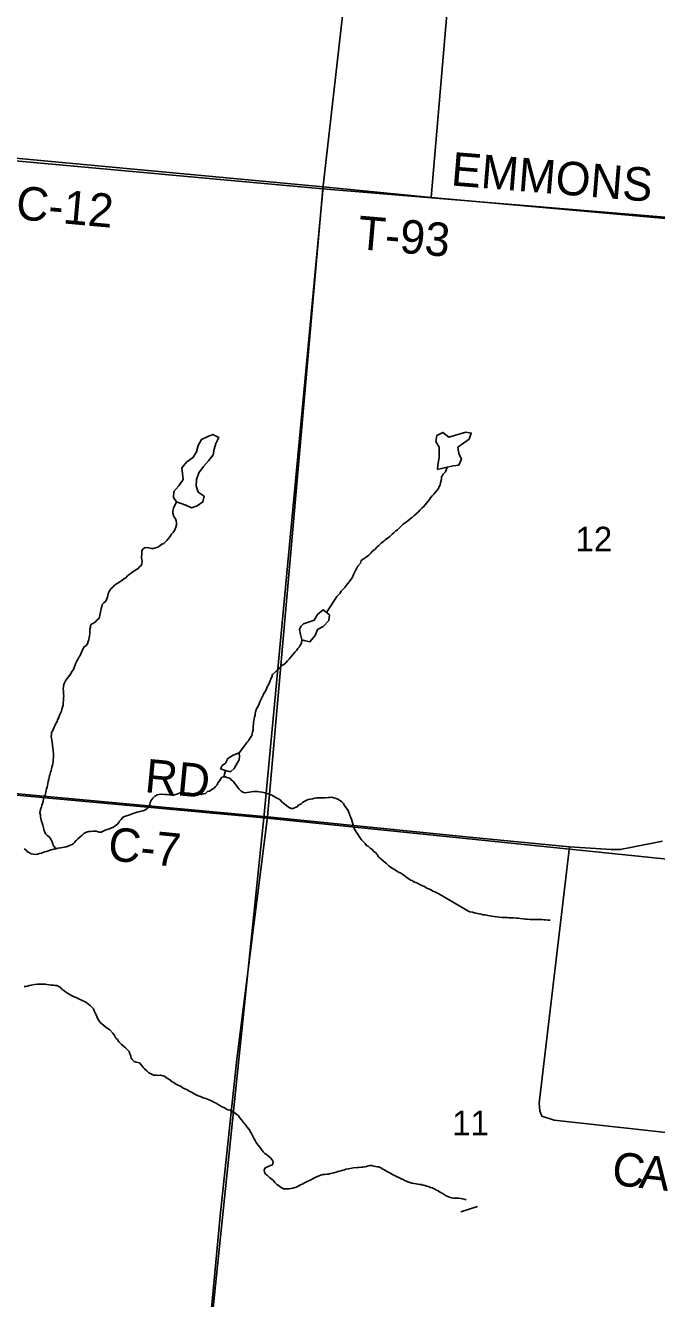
# Model space of a CAD drawing. Extents: x 1310247 to 1664935, y 284496 to 704931.
# Drawn here: x 1505542 to 1511194, y 520097 to 531499 of the extents above; entities that cross this region are included whole.
import ezdxf

# ---------------------------------------------------------------- set-up
doc = ezdxf.new("R2010")
doc.units = 0
for name, color, linetype in [('GM_X_County', 7, 'Continuous'), ('GM_X_County_Road_Text', 7, 'Continuous'), ('GM_X_County_Subdivision_Text', 7, 'Continuous'), ('GM_X_Minor_River', 7, 'Continuous'), ('GM_X_Minor_River_Text', 7, 'Continuous'), ('GM_X_Township_Road', 7, 'Continuous'), ('GM_X_Township_Subdivision', 7, 'Continuous'), ('GM_X_US_Location', 7, 'Continuous')]:
    doc.layers.add(name, color=color, linetype=linetype)

msp = doc.modelspace()

# ---------------------------------------------------------------- linework, layer by layer
at = {"layer": 'GM_X_County'}
for points in [[(1504265, 537212), (1509753, 536749), (1509752, 536706), (1509176, 529957), (1508208, 530054), (1503657, 530479)], [(1509752, 536706), (1515094, 536260), (1514552, 529479), (1513608, 529562), (1509176, 529957)], [(1503657, 530479), (1508208, 530054), (1507676, 524403), (1502528, 524873), (1503168, 530512)], [(1509176, 529957), (1513608, 529562), (1513069, 523850), (1507676, 524403), (1508208, 530054)], [(1502528, 524873), (1507676, 524403), (1507181, 519609), (1502005, 520104)], [(1513069, 523850), (1512615, 519096), (1507181, 519609), (1507676, 524403)]]:
    msp.add_lwpolyline(points, close=True, dxfattribs=at)
at = {"layer": 'GM_X_County_Road_Text'}
for points in [[(1505281, 530301), (1508204, 530036), (1508392, 531691)], [(1503046, 524841), (1507709, 524410), (1509518, 524229), (1510413, 524142), (1510508, 524135), (1510790, 524118), (1510869, 524118), (1510962, 524135), (1511247, 524193)]]:
    msp.add_lwpolyline(points, dxfattribs=at)
at = {"layer": 'GM_X_County_Subdivision_Text'}
for points in [[(1507709, 524410), (1508204, 530036)], [(1508204, 530036), (1513575, 529592)], [(1506888, 516735), (1507135, 519241), (1507286, 520838), (1507435, 522240), (1507709, 524410)], [(1512734, 520652), (1512746, 520753), (1512811, 521339), (1512781, 521407), (1512752, 521424), (1512685, 521430), (1510276, 521694), (1510168, 521730), (1510149, 521778), (1510143, 521846), (1510413, 524142)]]:
    msp.add_lwpolyline(points, dxfattribs=at)
at = {"layer": 'GM_X_Minor_River'}
for points in [[(1506894, 527231), (1506978, 527203), (1507029, 527178), (1507080, 527197), (1507131, 527231), (1507142, 527283), (1507089, 527319), (1507072, 527375), (1507075, 527432), (1507095, 527491), (1507137, 527549), (1507182, 527600), (1507224, 527653), (1507231, 527703), (1507246, 527755), (1507275, 527808), (1507220, 527836), (1507169, 527815), (1507118, 527792), (1507089, 527737), (1507075, 527679), (1507040, 527627), (1507038, 527625)], [(1509318, 527542), (1509373, 527555), (1509423, 527560), (1509447, 527613), (1509424, 527664), (1509413, 527721), (1509464, 527757), (1509515, 527794), (1509535, 527848), (1509485, 527855), (1509434, 527840), (1509384, 527826), (1509333, 527813), (1509280, 527854), (1509227, 527827), (1509218, 527773), (1509248, 527722), (1509247, 527674)], [(1507038, 527625), (1506987, 527590), (1506941, 527537), (1506948, 527487), (1506955, 527433), (1506915, 527377), (1506872, 527324), (1506869, 527272), (1506894, 527231)], [(1509247, 527674), (1509248, 527630), (1509235, 527562), (1509236, 527562)], [(1509236, 527562), (1509233, 527522), (1509318, 527542)], [(1508237, 526242), (1508209, 526266), (1508157, 526223), (1508128, 526171), (1508077, 526156), (1508033, 526139)], [(1508037, 525989), (1508089, 525979), (1508137, 526034), (1508158, 526088), (1508209, 526115), (1508258, 526170), (1508264, 526220), (1508237, 526242)], [(1508033, 526139), (1508012, 526120), (1507997, 526092), (1508004, 526044), (1508017, 525997), (1508037, 525989)], [(1507334, 524825), (1507364, 524818), (1507380, 524818), (1507412, 524843), (1507440, 524897), (1507455, 524921), (1507459, 524951), (1507456, 524983), (1507401, 524962), (1507354, 524933), (1507333, 524893), (1507305, 524872)], [(1507305, 524872), (1507290, 524842), (1507334, 524825)]]:
    msp.add_lwpolyline(points, dxfattribs=at)
at = {"layer": 'GM_X_Minor_River_Text'}
for points in [[(1508237, 526242), (1508311, 526353), (1508321, 526369), (1508330, 526385), (1508344, 526398), (1508357, 526412), (1508370, 526432), (1508380, 526445), (1508401, 526465), (1508415, 526484), (1508430, 526500), (1508445, 526519), (1508459, 526539), (1508470, 526557), (1508481, 526582), (1508492, 526604), (1508502, 526624), (1508511, 526638), (1508520, 526657), (1508543, 526683), (1508549, 526707), (1508593, 526737), (1508617, 526755), (1508634, 526774), (1508651, 526790), (1508673, 526809), (1508690, 526825), (1508706, 526842), (1508729, 526863), (1508750, 526879), (1508764, 526892), (1508785, 526908), (1508804, 526923), (1508826, 526943), (1508841, 526954), (1508859, 526972), (1508874, 526983), (1508895, 527003), (1508909, 527018), (1508926, 527032), (1508946, 527047), (1508963, 527059), (1508986, 527080), (1509004, 527092), (1509023, 527109), (1509041, 527124), (1509062, 527144), (1509074, 527157), (1509093, 527175), (1509106, 527189), (1509118, 527202), (1509137, 527222), (1509149, 527237), (1509160, 527253), (1509170, 527267), (1509185, 527286), (1509200, 527302), (1509216, 527321), (1509227, 527335), (1509240, 527353), (1509248, 527369), (1509255, 527382), (1509259, 527402), (1509264, 527422), (1509267, 527438), (1509269, 527456), (1509278, 527469), (1509282, 527481), (1509303, 527502), (1509318, 527542)], [(1506006, 525813), (1506015, 525827), (1506023, 525843), (1506032, 525856), (1506038, 525872), (1506045, 525886), (1506051, 525902), (1506058, 525916), (1506065, 525932), (1506087, 525947), (1506096, 525961), (1506104, 525980), (1506109, 525996), (1506111, 526014), (1506114, 526034), (1506117, 526048), (1506117, 526062), (1506117, 526076), (1506118, 526092), (1506123, 526110), (1506125, 526124), (1506134, 526138), (1506150, 526147), (1506170, 526157), (1506181, 526172), (1506199, 526186), (1506204, 526200), (1506209, 526218), (1506213, 526244), (1506216, 526260), (1506219, 526278), (1506225, 526295), (1506230, 526313), (1506244, 526327), (1506263, 526344), (1506269, 526358), (1506276, 526378), (1506279, 526394), (1506283, 526410), (1506288, 526424), (1506298, 526439), (1506307, 526453), (1506323, 526469), (1506340, 526486), (1506387, 526517), (1506406, 526528), (1506424, 526544), (1506441, 526553), (1506457, 526569), (1506472, 526582), (1506490, 526594), (1506507, 526607), (1506521, 526617), (1506535, 526625), (1506550, 526636), (1506562, 526650), (1506579, 526663), (1506583, 526677), (1506586, 526701), (1506585, 526715), (1506581, 526731), (1506581, 526745), (1506584, 526761), (1506583, 526777), (1506585, 526793), (1506594, 526807), (1506608, 526819), (1506626, 526822), (1506644, 526820), (1506658, 526817), (1506672, 526815), (1506686, 526814), (1506706, 526820), (1506727, 526827), (1506745, 526837), (1506762, 526852), (1506780, 526860), (1506795, 526873), (1506809, 526887), (1506820, 526900), (1506834, 526918), (1506851, 526942), (1506866, 526959), (1506876, 526977), (1506883, 526991), (1506889, 527006), (1506894, 527026), (1506895, 527044), (1506891, 527063), (1506886, 527079), (1506878, 527093), (1506869, 527111), (1506863, 527130), (1506862, 527148), (1506864, 527162), (1506869, 527179), (1506878, 527195), (1506894, 527231)], [(1507456, 524983), (1507513, 525059), (1507525, 525077), (1507536, 525090), (1507544, 525104), (1507557, 525122), (1507568, 525140), (1507572, 525155), (1507575, 525169), (1507581, 525189), (1507582, 525207), (1507582, 525223), (1507583, 525239), (1507584, 525257), (1507586, 525273), (1507589, 525291), (1507593, 525305), (1507598, 525323), (1507598, 525337), (1507601, 525351), (1507607, 525369), (1507614, 525383), (1507626, 525402), (1507635, 525422), (1507642, 525440), (1507650, 525460), (1507659, 525477), (1507670, 525501), (1507678, 525517), (1507689, 525535), (1507698, 525548), (1507704, 525566), (1507711, 525580), (1507719, 525594), (1507726, 525614), (1507734, 525631), (1507739, 525645), (1507748, 525665), (1507754, 525685), (1507785, 525712), (1507806, 525733), (1507825, 525751), (1507835, 525765), (1507856, 525776), (1507874, 525791), (1507889, 525809), (1507903, 525823), (1507912, 525836), (1507927, 525852), (1507937, 525866), (1507958, 525889), (1507972, 525905), (1507981, 525918), (1507993, 525932), (1508002, 525950), (1508013, 525964), (1508017, 525997)], [(1505814, 524123), (1505789, 524156), (1505788, 524170), (1505782, 524187), (1505773, 524205), (1505763, 524219), (1505750, 524234), (1505736, 524244), (1505722, 524259), (1505715, 524273), (1505709, 524287), (1505706, 524301), (1505700, 524323), (1505697, 524337), (1505691, 524356), (1505686, 524370), (1505681, 524396), (1505677, 524410), (1505676, 524428), (1505672, 524448), (1505675, 524462), (1505677, 524476), (1505684, 524500), (1505688, 524516), (1505693, 524530), (1505700, 524552), (1505704, 524568), (1505707, 524582), (1505711, 524596), (1505718, 524609), (1505724, 524633), (1505731, 524661), (1505736, 524677), (1505738, 524691), (1505743, 524711), (1505746, 524729), (1505750, 524747), (1505753, 524761), (1505757, 524781), (1505762, 524794), (1505766, 524810), (1505771, 524824), (1505776, 524842), (1505778, 524856), (1505783, 524874), (1505787, 524888), (1505790, 524902), (1505790, 524924), (1505793, 524942), (1505793, 524958), (1505792, 524980), (1505791, 524994), (1505789, 525008), (1505788, 525028), (1505784, 525048), (1505783, 525062), (1505781, 525076), (1505778, 525097), (1505776, 525115), (1505773, 525131), (1505774, 525151), (1505776, 525165), (1505783, 525179), (1505791, 525194), (1505800, 525214), (1505808, 525232), (1505815, 525246), (1505826, 525265), (1505830, 525279), (1505837, 525295), (1505843, 525313), (1505850, 525327), (1505860, 525345), (1505865, 525358), (1505869, 525374), (1505874, 525394), (1505879, 525414), (1505881, 525434), (1505882, 525448), (1505884, 525462), (1505883, 525476), (1505885, 525494), (1505884, 525508), (1505884, 525524), (1505883, 525540), (1505881, 525556), (1505882, 525576), (1505885, 525596), (1505891, 525610), (1505900, 525628), (1505913, 525648), (1505927, 525665), (1505942, 525685), (1505952, 525698), (1505957, 525712), (1505971, 525730), (1505978, 525750), (1505985, 525764), (1505991, 525781), (1506000, 525799), (1506006, 525813)], [(1506791, 524612), (1506811, 524610), (1506833, 524607), (1506851, 524606), (1506869, 524606), (1506889, 524611), (1506912, 524619), (1506928, 524626), (1506946, 524628), (1506968, 524627), (1506990, 524624), (1507008, 524622), (1507026, 524619), (1507048, 524616), (1507062, 524614), (1507082, 524613), (1507102, 524613), (1507116, 524612), (1507134, 524616), (1507153, 524621), (1507173, 524637), (1507190, 524642), (1507210, 524656), (1507231, 524669), (1507245, 524684), (1507258, 524698), (1507266, 524716), (1507281, 524733), (1507289, 524747), (1507302, 524765), (1507318, 524770), (1507332, 524768), (1507346, 524764), (1507360, 524759), (1507374, 524753), (1507388, 524740), (1507405, 524728), (1507415, 524713), (1507428, 524695), (1507442, 524678), (1507457, 524658), (1507473, 524641), (1507489, 524631), (1507507, 524626), (1507527, 524628), (1507549, 524633), (1507563, 524635), (1507583, 524638), (1507601, 524637), (1507621, 524637), (1507635, 524634), (1507659, 524632), (1507673, 524629), (1507687, 524627), (1507713, 524618), (1507733, 524611), (1507749, 524605), (1507779, 524588), (1507794, 524579), (1507808, 524571), (1507824, 524562), (1507835, 524548), (1507857, 524531), (1507879, 524513), (1507902, 524494), (1507926, 524485), (1507940, 524487), (1507958, 524494), (1507975, 524502), (1507987, 524515), (1508010, 524527), (1508024, 524538), (1508038, 524548), (1508061, 524559), (1508075, 524565), (1508093, 524568), (1508114, 524573), (1508134, 524579), (1508148, 524580), (1508164, 524582), (1508180, 524581), (1508194, 524581), (1508210, 524581), (1508226, 524580), (1508253, 524583), (1508267, 524585), (1508285, 524586), (1508301, 524582), (1508315, 524577), (1508338, 524569), (1508354, 524560), (1508376, 524545), (1508391, 524531), (1508397, 524515), (1508416, 524488), (1508432, 524467), (1508439, 524451), (1508443, 524437), (1508448, 524423), (1508456, 524405), (1508461, 524390)], [(1507318, 524770), (1507334, 524825)], [(1505529, 524124), (1505545, 524116), (1505558, 524101), (1505576, 524091), (1505592, 524080), (1505612, 524076), (1505632, 524075), (1505650, 524078), (1505668, 524082), (1505686, 524087), (1505711, 524097), (1505729, 524100), (1505749, 524107), (1505768, 524115), (1505782, 524118), (1505798, 524122), (1505814, 524123), (1505832, 524129), (1505857, 524132), (1505873, 524136), (1505889, 524139), (1505905, 524143), (1505930, 524152), (1505950, 524159), (1505968, 524169), (1505981, 524182), (1505997, 524198), (1506012, 524214), (1506029, 524229), (1506049, 524248), (1506066, 524262), (1506088, 524273), (1506107, 524279), (1506125, 524280), (1506149, 524283), (1506175, 524283), (1506201, 524274), (1506219, 524275), (1506233, 524279), (1506256, 524292), (1506274, 524298), (1506294, 524305), (1506311, 524312), (1506329, 524320), (1506345, 524331), (1506366, 524345), (1506377, 524359), (1506385, 524372), (1506398, 524386), (1506412, 524404), (1506429, 524413), (1506455, 524422), (1506469, 524426), (1506483, 524433), (1506498, 524439), (1506512, 524445), (1506526, 524446), (1506540, 524452), (1506557, 524455), (1506577, 524461), (1506593, 524464), (1506617, 524475), (1506634, 524489), (1506651, 524508), (1506655, 524522), (1506660, 524538), (1506671, 524562), (1506683, 524578), (1506700, 524597), (1506722, 524608), (1506740, 524612), (1506761, 524613), (1506791, 524612)], [(1508461, 524390), (1508467, 524370), (1508474, 524348), (1508479, 524330), (1508487, 524307), (1508498, 524287), (1508511, 524267), (1508521, 524250), (1508530, 524234), (1508552, 524205), (1508567, 524189), (1508583, 524172), (1508596, 524154), (1508610, 524147), (1508629, 524131), (1508643, 524120), (1508663, 524102), (1508678, 524091), (1508692, 524073), (1508705, 524054), (1508727, 524033), (1508748, 524013), (1508762, 524002), (1508776, 523992), (1508797, 523971), (1508821, 523954), (1508842, 523942), (1508866, 523927), (1508884, 523916), (1508903, 523906), (1508921, 523895), (1508945, 523878), (1508960, 523866), (1508974, 523857), (1508990, 523845), (1509004, 523841), (1509021, 523830), (1509039, 523823), (1509053, 523817), (1509069, 523808), (1509085, 523800), (1509099, 523794), (1509115, 523787), (1509130, 523776), (1509144, 523770), (1509160, 523764), (1509178, 523753), (1509191, 523745), (1509207, 523738), (1509225, 523729), (1509243, 523721), (1509505, 523568)], [(1509505, 523568), (1509523, 523560), (1509545, 523556), (1509563, 523551), (1509577, 523547), (1509591, 523545), (1509605, 523543), (1509623, 523538), (1509641, 523534), (1509659, 523532), (1509683, 523527), (1509703, 523523), (1509719, 523520), (1509740, 523518), (1509764, 523514), (1509784, 523511), (1509810, 523509), (1509826, 523508), (1509840, 523508), (1509860, 523508), (1509874, 523505), (1509898, 523505), (1509914, 523505), (1509943, 523502), (1509957, 523502), (1509973, 523500), (1509999, 523497), (1510019, 523495), (1510035, 523495), (1510063, 523492), (1510085, 523492), (1510101, 523493), (1510119, 523493), (1510134, 523493), (1510148, 523492), (1510166, 523492), (1510186, 523490), (1510202, 523489), (1510222, 523487), (1510240, 523485)], [(1505530, 522890), (1505545, 522891), (1505561, 522895), (1505577, 522900), (1505595, 522904), (1505624, 522909), (1505646, 522912), (1505670, 522913), (1505686, 522913), (1505702, 522912), (1505718, 522912), (1505734, 522909), (1505756, 522907), (1505772, 522904), (1505794, 522902), (1505808, 522901), (1505822, 522899), (1505836, 522894), (1505854, 522884), (1505869, 522867), (1505885, 522855), (1505899, 522844), (1505918, 522832), (1505948, 522815), (1505978, 522800), (1505997, 522793), (1506011, 522785), (1506025, 522778), (1506051, 522765), (1506077, 522753), (1506094, 522742), (1506120, 522721), (1506135, 522705), (1506151, 522690), (1506158, 522674), (1506175, 522639), (1506181, 522623), (1506190, 522603), (1506200, 522586), (1506211, 522570), (1506227, 522556)], [(1506227, 522556), (1506244, 522541), (1506262, 522528), (1506284, 522512), (1506297, 522503), (1506323, 522474), (1506340, 522452), (1506351, 522429), (1506365, 522417), (1506378, 522397), (1506398, 522374), (1506417, 522359), (1506439, 522341), (1506452, 522328), (1506470, 522308), (1506477, 522287), (1506485, 522271), (1506490, 522251), (1506498, 522237), (1506515, 522220), (1506533, 522213), (1506549, 522211), (1506563, 522209), (1506580, 522186), (1506596, 522165), (1506609, 522153), (1506629, 522136), (1506648, 522118), (1506670, 522107), (1506690, 522098), (1506714, 522098), (1506730, 522095), (1506752, 522096), (1506772, 522092), (1506786, 522087), (1506806, 522073), (1506825, 522062), (1506839, 522052), (1506857, 522037), (1506871, 522031), (1506890, 522018), (1506914, 522005), (1506936, 521995), (1506955, 521982), (1506977, 521971), (1506991, 521965), (1507015, 521952), (1507030, 521946), (1507058, 521927), (1507090, 521912), (1507110, 521905), (1507133, 521894), (1507157, 521888), (1507171, 521883), (1507193, 521872), (1507207, 521866), (1507234, 521853), (1507250, 521847), (1507268, 521836), (1507284, 521826), (1507299, 521817), (1507323, 521804), (1507341, 521794), (1507357, 521787), (1507375, 521783), (1507396, 521768), (1507412, 521762), (1507436, 521745), (1507449, 521732), (1507459, 521718), (1507476, 521697), (1507496, 521673), (1507517, 521650), (1507528, 521632), (1507544, 521611), (1507559, 521585), (1507569, 521568), (1507582, 521544), (1507591, 521526), (1507599, 521511), (1507608, 521495), (1507622, 521474), (1507641, 521452), (1507655, 521433), (1507670, 521411), (1507687, 521396), (1507701, 521388), (1507719, 521373), (1507734, 521359), (1507750, 521340), (1507761, 521320), (1507757, 521306), (1507750, 521292), (1507736, 521287), (1507722, 521281), (1507704, 521274), (1507689, 521266), (1507681, 521246), (1507682, 521228), (1507693, 521212), (1507711, 521199)], [(1507711, 521199), (1507729, 521179), (1507742, 521170), (1507760, 521156), (1507775, 521137), (1507793, 521119), (1507807, 521110), (1507820, 521100), (1507840, 521085), (1507854, 521079), (1507868, 521078), (1507884, 521078), (1507904, 521079), (1507918, 521081), (1507936, 521084), (1507965, 521095), (1507979, 521101), (1508004, 521116), (1508020, 521122), (1508047, 521137), (1508065, 521144), (1508081, 521152), (1508104, 521163), (1508120, 521171), (1508135, 521182), (1508163, 521193), (1508187, 521203), (1508206, 521208), (1508222, 521209), (1508240, 521211), (1508256, 521212), (1508274, 521216), (1508303, 521223), (1508325, 521230), (1508351, 521238), (1508370, 521241), (1508384, 521247), (1508398, 521250), (1508412, 521254), (1508434, 521259), (1508465, 521264), (1508481, 521266), (1508513, 521269), (1508529, 521270), (1508547, 521272), (1508562, 521273), (1508580, 521277), (1508596, 521280), (1508612, 521284), (1508626, 521287), (1508642, 521287), (1508662, 521282), (1508676, 521280), (1508694, 521275), (1508708, 521275), (1508724, 521268), (1508744, 521256), (1508758, 521249), (1508779, 521236), (1508799, 521226), (1508813, 521217), (1508829, 521209), (1508848, 521200), (1508872, 521187), (1508892, 521177), (1508906, 521170), (1508924, 521162), (1508937, 521153), (1508953, 521147), (1508967, 521142), (1508985, 521136), (1509003, 521129), (1509021, 521127), (1509041, 521124), (1509055, 521122), (1509069, 521119), (1509087, 521117), (1509103, 521112), (1509121, 521108), (1509135, 521103), (1509151, 521099), (1509168, 521092), (1509184, 521088), (1509208, 521075), (1509224, 521068), (1509238, 521062), (1509259, 521047), (1509275, 521039), (1509293, 521028), (1509311, 521018), (1509324, 521011), (1509340, 521005), (1509358, 520998), (1509374, 520996), (1509388, 520997), (1509406, 520997), (1509424, 520996), (1509442, 520993), (1509456, 520989), (1509472, 520987), (1509488, 520982)], [(1509440, 520874), (1509591, 520921)]]:
    msp.add_lwpolyline(points, dxfattribs=at)

# ---------------------------------------------------------------- texts
at = {"layer": 'GM_X_Township_Road'}
for s, rotation, p in [('C-12', 354.8369, (1505449, 529765)), ('RD', 354.5372, (1506603, 524633)), ('C-7', 354.472, (1506273, 524023))]:
    msp.add_text(s, height=300, rotation=rotation, dxfattribs=at).set_placement(p)
at = {"layer": 'GM_X_Township_Subdivision'}
for s, rotation, p in [('EMMONS', 355.3015, (1509347, 530067)), ('T-93', 355.0608, (1508509, 529497)), ('C', 353.7348, (1510785, 521116)), ('A', 353.733, (1511030, 521089))]:
    msp.add_text(s, height=300, rotation=rotation, dxfattribs=at).set_placement(p)
at = {"layer": 'GM_X_US_Location'}
for s, p in [('12', (1510468, 526788)), ('11', (1509364, 521559))]:
    msp.add_text(s, height=221, rotation=0, dxfattribs=at).set_placement(p)

doc.saveas('drawing.dxf')
